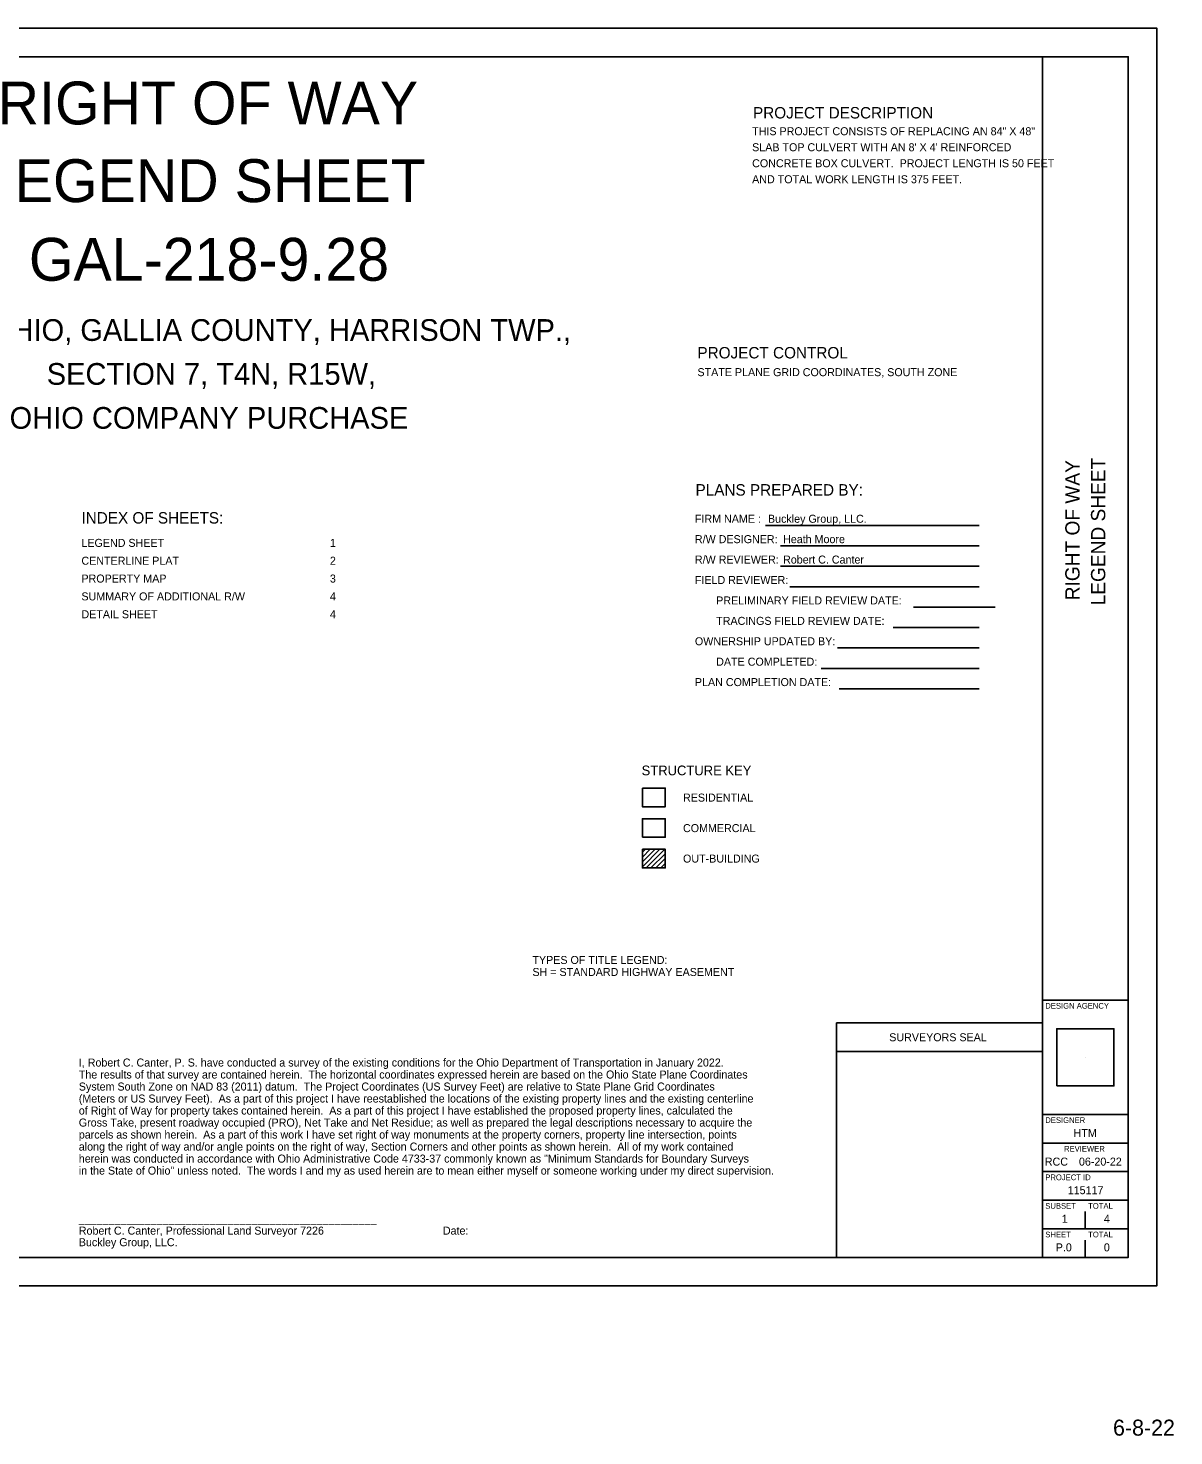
# Model space of a CAD drawing. Extents: x 0 to 34.3, y -4.1 to 22.
# Drawn here: x 14.26 to 34.3, y -2.62 to 22 of the extents above; entities that cross this region are included whole.
import ezdxf

# ---------------------------------------------------------------- set-up
doc = ezdxf.new("R2010")
doc.units = 0
for name, color, linetype in [('GM_X_Adjacent_County', 7, 'Continuous'), ('GM_X_Adjacent_County_Text', 7, 'Continuous'), ('GM_X_County', 7, 'Continuous'), ('GM_X_Section', 7, 'Continuous'), ('GM_X_Township', 7, 'Continuous')]:
    doc.layers.add(name, color=color, linetype=linetype)

msp = doc.modelspace()

# ---------------------------------------------------------------- linework, layer by layer
at = {"layer": 'GM_X_Adjacent_County'}
for p, q in [((27.154, 13.302), (30.891, 13.302)), ((27.418, 12.945), (30.891, 12.945)), ((27.418, 12.587), (30.891, 12.587)), ((27.582, 12.23), (30.891, 12.23)), ((29.745, 11.873), (31.175, 11.873)), ((29.387, 11.516), (30.891, 11.516)), ((28.418, 11.159), (30.891, 11.159)), ((28.132, 10.801), (30.891, 10.801)), ((28.447, 10.445), (30.891, 10.445)), ((25.005, 7.636), (25.006, 7.638)), ((25.005, 7.586), (25.056, 7.638)), ((25.005, 7.501), (25.141, 7.638)), ((25.005, 7.417), (25.226, 7.638)), ((25.005, 7.332), (25.311, 7.638)), ((25.069, 7.312), (25.395, 7.638)), ((25.154, 7.312), (25.402, 7.56)), ((25.239, 7.312), (25.402, 7.475)), ((25.324, 7.312), (25.402, 7.39)), ((25.005, 7.316), (25.01, 7.312))]:
    msp.add_line(p, q, dxfattribs=at)
for points in [[(25.005, 8.708), (25.402, 8.708), (25.402, 8.382), (25.005, 8.382)], [(25.005, 7.638), (25.402, 7.638), (25.402, 7.312), (25.005, 7.312)]]:
    msp.add_lwpolyline(points, close=True, dxfattribs=at)
at = {"layer": 'GM_X_Adjacent_County_Text'}
msp.add_lwpolyline([(25.005, 7.847), (25.402, 7.847), (25.402, 8.173), (25.005, 8.173)], close=True, dxfattribs=at)
at = {"layer": 'GM_X_County'}
for p, q in [((32, 0.5), (32, 21.5)), ((32, 5), (33.5, 5)), ((32, 3), (33.5, 3)), ((32, 2.5), (33.5, 2.5)), ((32, 2), (33.5, 2)), ((32, 1.5), (33.5, 1.5)), ((32, 1), (33.5, 1))]:
    msp.add_line(p, q, dxfattribs=at)
msp.add_lwpolyline([(1.5, 21.5), (33.5, 21.5), (33.5, 0.5), (1.5, 0.5)], close=True, dxfattribs=at)
at = {"layer": 'GM_X_Section'}
msp.add_lwpolyline([(0, 0), (34, 0), (34, 22), (0, 22)], close=True, dxfattribs=at)
at = {"layer": 'GM_X_Township'}
for p, q in [((28.4, 4.1), (32, 4.1)), ((32.75, 4), (32.75, 4)), ((32.75, 1), (32.75, 1.3)), ((32.75, 0.5), (32.75, 0.8)), ((32.375, 0.675), (32.375, 0.675))]:
    msp.add_line(p, q, dxfattribs=at)
for points in [[(28.4, 4.6), (32, 4.6), (32, 0.5), (28.4, 0.5)], [(32.25, 3.5), (33.25, 3.5), (33.25, 4.5), (32.25, 4.5)]]:
    msp.add_lwpolyline(points, close=True, dxfattribs=at)

# ---------------------------------------------------------------- texts
at = {"layer": 'GM_X_Adjacent_County'}
for s, height, p in [('PROJECT DESCRIPTION', 0.2, (26.938, 20.42)), ('THIS PROJECT CONSISTS OF REPLACING AN 84" X 48"', 0.14, (26.923, 20.127)), ("SLAB TOP CULVERT WITH AN 8' X 4' REINFORCED", 0.14, (26.923, 19.847)), ('CONCRETE BOX CULVERT.  PROJECT LENGTH IS 50 FEET', 0.14, (26.923, 19.567)), ('AND TOTAL WORK LENGTH IS 375 FEET.', 0.14, (26.923, 19.287)), ('PROJECT CONTROL', 0.2, (25.966, 16.223)), ('STATE PLANE GRID COORDINATES, SOUTH ZONE', 0.14, (25.967, 15.913)), ('PLANS PREPARED BY:', 0.2, (25.933, 13.824)), ('FIRM NAME :', 0.14, (25.922, 13.349)), ('Buckley Group, LLC.', 0.14, (27.2, 13.349)), ('R/W DESIGNER:', 0.14, (25.922, 12.992)), ('Heath Moore', 0.14, (27.464, 12.992)), ('R/W REVIEWER:', 0.14, (25.922, 12.635)), ('Robert C. Canter', 0.14, (27.464, 12.635)), ('FIELD REVIEWER:', 0.14, (25.922, 12.278)), ('PRELIMINARY FIELD REVIEW DATE:', 0.14, (26.294, 11.92)), ('TRACINGS FIELD REVIEW DATE:', 0.14, (26.294, 11.563)), ('OWNERSHIP UPDATED BY:', 0.14, (25.922, 11.206)), ('DATE COMPLETED:', 0.14, (26.294, 10.849)), ('PLAN COMPLETION DATE:', 0.14, (25.922, 10.492)), ('STRUCTURE KEY', 0.17, (24.99, 8.932)), ('RESIDENTIAL', 0.14, (25.714, 8.472)), ('COMMERCIAL', 0.14, (25.714, 7.938)), ('OUT-BUILDING', 0.14, (25.714, 7.405)), ('TYPES OF TITLE LEGEND:', 0.14, (23.08, 5.632)), ('SH = STANDARD HIGHWAY EASEMENT', 0.14, (23.08, 5.422)), ('I, Robert C. Canter, P. S. have conducted a survey of the existing conditions for the Ohio Department of Transportation in January 2022.', 0.14, (15.146, 3.838)), ('The results of that survey are contained herein.  The horizontal coordinates expressed herein are based on the Ohio State Plane Coordinates', 0.14, (15.146, 3.628)), ('System South Zone on NAD 83 (2011) datum.  The Project Coordinates (US Survey Feet) are relative to State Plane Grid Coordinates', 0.14, (15.146, 3.418)), ('(Meters or US Survey Feet).  As a part of this project I have reestablished the locations of the existing property lines and the existing centerline', 0.14, (15.146, 3.208)), ('of Right of Way for property takes contained herein.  As a part of this project I have established the proposed property lines, calculated the', 0.14, (15.146, 2.998)), ('Gross Take, present roadway occupied (PRO), Net Take and Net Residue; as well as prepared the legal descriptions necessary to acquire the', 0.14, (15.146, 2.788)), ('parcels as shown herein.  As a part of this work I have set right of way monuments at the property corners, property line intersection, points', 0.14, (15.146, 2.578)), ('along the right of way and/or angle points on the right of way, Section Corners and other points as shown herein.  All of my work contained', 0.14, (15.146, 2.368)), ('herein was conducted in accordance with Ohio Administrative Code 4733-37 commonly known as "Minimum Standards for Boundary Surveys', 0.14, (15.146, 2.158)), ('in the State of Ohio" unless noted.  The words I and my as used herein are to mean either myself or someone working under my direct supervision.', 0.14, (15.146, 1.948)), ('__________________________________________________                                        ', 0.14, (15.146, 1.108)), ('Robert C. Canter, Professional Land Surveyor 7226                                        Date:                  ', 0.14, (15.146, 0.898)), ('Buckley Group, LLC.', 0.14, (15.146, 0.695)), ('6-8-22', 0.28, (33.235, -2.618))]:
    msp.add_text(s, height=height, dxfattribs=at).set_placement(p)
at = {"layer": 'GM_X_Township'}
for s, height, p in [('RIGHT OF WAY', 0.75, (13.727, 20.316)), ('LEGEND SHEET', 0.75, (13.468, 18.957)), ('GAL-218-9.28', 0.75, (14.273, 17.582)), ('STATE OF OHIO, GALLIA COUNTY, HARRISON TWP.,', 0.38, (10.966, 16.53)), ('SECTION 7, T4N, R15W,', 0.38, (14.585, 15.762)), ('OHIO COMPANY PURCHASE', 0.38, (13.936, 14.993)), ('INDEX OF SHEETS:', 0.2, (15.192, 13.335)), ('LEGEND SHEET', 0.14, (15.192, 12.927)), ('1', 0.14, (19.538, 12.927)), ('CENTERLINE PLAT', 0.14, (15.192, 12.615)), ('2', 0.14, (19.538, 12.615)), ('PROPERTY MAP', 0.14, (15.192, 12.303)), ('3', 0.14, (19.538, 12.303)), ('SUMMARY OF ADDITIONAL R/W', 0.14, (15.192, 11.991)), ('4', 0.14, (19.538, 11.991)), ('DETAIL SHEET', 0.14, (15.192, 11.679)), ('4', 0.14, (19.538, 11.679)), ('DESIGN AGENCY', 0.1, (32.05, 4.85)), ('SURVEYORS SEAL', 0.14, (29.321, 4.28)), ('DESIGNER', 0.1, (32.05, 2.85)), ('HTM', 0.14, (32.545, 2.605)), ('RCC', 0.14, (32.042, 2.105)), ('REVIEWER', 0.1, (32.378, 2.35)), ('06-20-22', 0.14, (32.639, 2.105)), ('PROJECT ID', 0.1, (32.05, 1.85)), ('115117', 0.14, (32.443, 1.605)), ('SUBSET', 0.1, (32.05, 1.35)), ('1', 0.14, (32.339, 1.105)), ('TOTAL', 0.1, (32.8, 1.35)), ('4', 0.14, (33.075, 1.105)), ('SHEET', 0.1, (32.05, 0.85)), ('P.0', 0.14, (32.233, 0.605)), ('TOTAL', 0.1, (32.8, 0.85)), ('0', 0.14, (33.075, 0.605))]:
    msp.add_text(s, height=height, dxfattribs=at).set_placement(p)
for s, p in [('RIGHT OF WAY', (32.65, 11.993)), ('LEGEND SHEET', (33.1, 11.904))]:
    msp.add_text(s, height=0.25, rotation=90, dxfattribs=at).set_placement(p)

doc.saveas('drawing.dxf')
